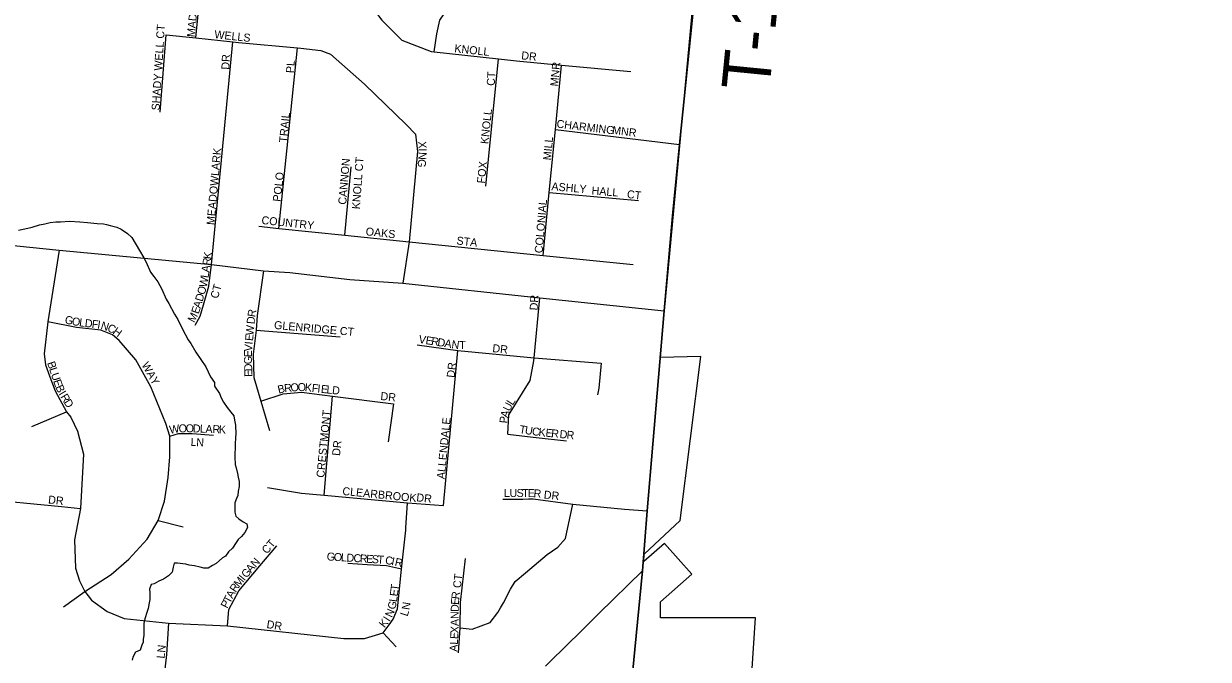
# Model space of a CAD drawing. Extents: x 1310247 to 1552180, y 377264 to 706493.
# Drawn here: x 1441493 to 1448897, y 490170 to 494144 of the extents above; entities that cross this region are included whole.
import ezdxf

# ---------------------------------------------------------------- set-up
doc = ezdxf.new("R2010")
doc.units = 0
for name, color, linetype in [('GM_X_Adjacent_County', 7, 'Continuous'), ('GM_X_Corporation', 7, 'Continuous'), ('GM_X_County', 7, 'Continuous'), ('GM_X_Minor_River', 7, 'Continuous'), ('GM_X_Township', 7, 'Continuous'), ('GM_X_Township_Road', 7, 'Continuous'), ('GM_X_Township_Road_Text', 7, 'Continuous'), ('GM_X_Township_Subdivision', 7, 'Continuous'), ('GM_X_Township_Subdivision_Text', 7, 'Continuous'), ('GM_X_US_Route', 7, 'Continuous')]:
    doc.layers.add(name, color=color, linetype=linetype)

msp = doc.modelspace()

# ---------------------------------------------------------------- linework, layer by layer
at = {"layer": 'GM_X_Adjacent_County'}
msp.add_lwpolyline([(1444758.9, 484386.7), (1444847.2, 485340), (1444871.9, 485606.9), (1444945, 486395.4), (1445051.2, 487540.6), (1445054.9, 487578.1), (1445360.5, 490723.4), (1445389.8, 491098.1), (1445497, 492347.4), (1445549.2, 492941.9), (1445592.7, 493387.5), (1445681.3, 494266.4), (1445732.6, 494862.7), (1445785.8, 495446.6), (1445993, 497703.6), (1446026.9, 498075.2), (1446211.6, 500082.3), (1446320.8, 501270), (1446353.3, 501607.9), (1446491.2, 503041.2)], dxfattribs=at)
at = {"layer": 'GM_X_Corporation'}
msp.add_lwpolyline([(1449213.9, 489565.2), (1448718.7, 488633.8), (1447946.3, 488728.6), (1447946.3, 489474.1), (1446677.2, 489572.9), (1446654.2, 489182.6), (1446017.2, 489196.3), (1446083.4, 489751.4), (1446023.8, 489764), (1446066.6, 490429.5), (1445474.1, 490429.5), (1445474.1, 490529.5), (1445668.9, 490702.2), (1445499.3, 490893.6), (1445370.2, 490780.2), (1445371.7, 490827.7), (1445596.3, 491036.6), (1445726.4, 492063.1), (1445470.2, 492057.2), (1445876.5, 496431.2)], dxfattribs=at)
at = {"layer": 'GM_X_County'}
msp.add_lwpolyline([(1446491.2, 503041.2), (1446353.3, 501607.9), (1446320.8, 501270), (1446211.6, 500082.3), (1446026.9, 498075.2), (1445993, 497703.6), (1445785.8, 495446.6), (1445732.6, 494862.7), (1445681.3, 494266.4), (1445592.7, 493387.5), (1445549.2, 492941.9), (1445497, 492347.4), (1445389.8, 491098.1), (1445360.5, 490723.4), (1445054.9, 487578.1), (1445051.2, 487540.6), (1444945, 486395.4), (1444871.9, 485606.9), (1444847.2, 485340), (1444758.9, 484386.7)], dxfattribs=at)
at = {"layer": 'GM_X_Minor_River'}
for points in [[(1441461.3, 492853.2), (1441519.9, 492865.4), (1441546.1, 492870.6), (1441592.7, 492885.3), (1441625, 492892.3), (1441659.4, 492901.3), (1441693.6, 492904.3), (1441723.8, 492905.3), (1441780.1, 492909.6), (1441844.1, 492903.7), (1441892.2, 492900.2), (1441952.2, 492894.3), (1441992.3, 492893.1), (1442010.3, 492888.6), (1442034.1, 492881.8), (1442076, 492870.5), (1442101.7, 492859.7), (1442143.1, 492832.3), (1442168.4, 492807.5), (1442218.2, 492725.7), (1442244.9, 492678.7), (1442258.2, 492652.2), (1442286.4, 492589.1), (1442307.7, 492562.4), (1442330.8, 492529.5), (1442357.6, 492484.6), (1442383.8, 492421.5), (1442401.1, 492394.9), (1442435.3, 492327.6), (1442456.4, 492294.9), (1442486.7, 492233.8), (1442520.8, 492166.5), (1442538.2, 492143.9), (1442568.8, 492090.8), (1442632.3, 491998.5), (1442660.5, 491935.4), (1442685.6, 491900.5), (1442686.9, 491876.4), (1442717.7, 491831.3), (1442726.9, 491804.9), (1442742.1, 491776.4), (1442765.3, 491743.6), (1442788.5, 491714.8), (1442805.9, 491692.1), (1442811.1, 491663.9), (1442816.2, 491633.6), (1442818.6, 491577.3), (1442818, 491559.3), (1442814.7, 491513.2), (1442812.3, 491433), (1442815, 491386.8), (1442822.4, 491366.5), (1442829.4, 491332.1), (1442834.7, 491307.9), (1442840, 491281.7), (1442841, 491249.5)], [(1442841, 491249.5), (1442834.2, 491221.6), (1442831.4, 491193.6), (1442822.8, 491175.8), (1442814, 491148), (1442812.3, 491089.8), (1442819.6, 491065.5), (1442837.1, 491046.9), (1442864.7, 491030), (1442888.4, 491017.2), (1442891.7, 490993.1), (1442874.7, 490961.5), (1442854, 490938), (1442833.3, 490918.6), (1442820.7, 490900.9), (1442797.6, 490865.5), (1442772.9, 490842.2), (1442754, 490814.6), (1442735.6, 490803.1), (1442696.4, 490768.2), (1442674, 490756.9), (1442645.4, 490739.7), (1442619.3, 490738.5), (1442595.4, 490745.2), (1442561.6, 490754.3), (1442527.5, 490757.3), (1442507.7, 490764), (1442487.7, 490766.6), (1442453.7, 490771.6), (1442433.6, 490770.2), (1442426.9, 490746.4), (1442421.9, 490714.4), (1442399.2, 490691), (1442366.4, 490669.9), (1442338, 490658.8), (1442309.4, 490641.6), (1442289.2, 490638.2), (1442280.3, 490608.3), (1442281.7, 490586.2), (1442282.5, 490544), (1442277.8, 490522.1), (1442270.8, 490488.2), (1442264.2, 490468.3), (1442250.8, 490422.6), (1442243.9, 490392.7), (1442245.2, 490370.6), (1442243.8, 490320.4), (1442241, 490294.4), (1442240.5, 490276.4), (1442231.9, 490258.6), (1442220.9, 490226.8), (1442192.5, 490213.6), (1442175.5, 490184), (1442170.9, 490164.1)]]:
    msp.add_lwpolyline(points, dxfattribs=at)
at = {"layer": 'GM_X_Township'}
msp.add_lwpolyline([(1446491.2, 503041.2), (1446353.3, 501607.9), (1446320.8, 501270), (1446211.6, 500082.3), (1446026.9, 498075.2), (1445993, 497703.6), (1445785.8, 495446.6), (1445732.6, 494862.7), (1445681.3, 494266.4), (1445592.7, 493387.5), (1445549.2, 492941.9), (1445497, 492347.4), (1445389.8, 491098.1), (1445360.5, 490723.4), (1445054.9, 487578.1), (1445051.2, 487540.6), (1444945, 486395.4), (1444871.9, 485606.9), (1444847.2, 485340), (1444758.9, 484386.7)], dxfattribs=at)
at = {"layer": 'GM_X_Township_Road'}
for points in [[(1445639.5, 493851.8), (1445681.3, 494266.4), (1445732.6, 494862.7), (1445785.8, 495446.6), (1445833.6, 495967.5)], [(1445531.1, 492735.1), (1445549.2, 492941.9), (1445592.6, 493387.5), (1445639.5, 493851.8)], [(1437774.4, 493620), (1438322.3, 493469.7), (1439008.5, 493285.9), (1439273.8, 493215.4), (1439579.9, 493129.2), (1439710.8, 493101.7), (1440082, 493005), (1440679.8, 492841.4), (1441204.7, 492780.6), (1441714.2, 492726.8), (1442667.4, 492637.5), (1442992.2, 492599.4), (1443157.4, 492587.5), (1443532.5, 492544.6), (1443863.8, 492520.3), (1444719.2, 492429.1), (1445497, 492347.4)], [(1445480, 492149.6), (1445497, 492347.4), (1445531.1, 492735.1)], [(1445354.3, 490658.8), (1445360.5, 490723.4), (1445389.8, 491098.1), (1445480, 492149.6)], [(1444837.4, 485233.9), (1444847.2, 485340), (1444871.9, 485606.9), (1444945, 486395.5), (1445051.2, 487540.6), (1445054.9, 487578.2), (1445354.3, 490658.8)]]:
    msp.add_lwpolyline(points, dxfattribs=at)
at = {"layer": 'GM_X_Township_Subdivision'}
for points in [[(1443474.7, 494549.8), (1443526.5, 494442.8), (1443613.9, 494324.9), (1443731.8, 494165.8), (1443857, 494040.6), (1444040.7, 493970.2), (1444059, 493968.2), (1444460, 493924.2), (1444572.5, 493911.8), (1444855.1, 493885.1), (1445288.1, 493844.2)], [(1442569.2, 494054.1), (1442589, 494245.3), (1442590, 494255.5)], [(1444059, 493968.2), (1444075.7, 494079.4), (1444093.9, 494165.3), (1444120.4, 494205.1)], [(1442346, 493590.6), (1442384.6, 494073.1)], [(1442384.6, 494073.1), (1442569.2, 494054.1), (1442800.1, 494030.4), (1442835.4, 494026.7), (1443204.6, 493992.4), (1443225.1, 493990.5), (1443349.7, 493975.6), (1443411.9, 493952.3), (1443623.1, 493765.7), (1443883.9, 493513.7), (1443941.9, 493453.6), (1443954.2, 493343.7), (1443902.4, 492780), (1443863.8, 492520.3)], [(1442667.4, 492637.5), (1442800.1, 494030.4)], [(1443089, 492863.7), (1443204.6, 493992.4)], [(1444381, 493128.5), (1444460, 493924.2)], [(1444739.8, 492693.8), (1444778, 493088.3), (1444816.1, 493482.3), (1444855.1, 493885.1)], [(1444816.1, 493482.3), (1445592.6, 493387.5)], [(1443499.9, 492821.4), (1443539.2, 493249.5)], [(1444778, 493088.3), (1445336.5, 493037.3)], [(1442963.6, 492876.6), (1443089, 492863.7), (1443499.9, 492821.4), (1443902.4, 492780), (1444739.8, 492693.8), (1445302.2, 492637.4)], [(1441714.2, 492726.8), (1441643.9, 492278.6), (1441621.8, 492079.3), (1441628.8, 492009.9), (1441656.5, 491936.3), (1441689.5, 491848.6), (1441760.6, 491716.7), (1441787.4, 491683.2), (1441830, 491596.9), (1441866.4, 491451.2), (1441849.1, 491112), (1441811, 490916.8), (1441817.9, 490739.8), (1441842.2, 490660), (1441876.4, 490593.2), (1441916.8, 490538.5), (1442015.7, 490469.1), (1442121.5, 490424), (1442399.1, 490395.4), (1442766.8, 490378.9), (1443493.3, 490299.9), (1443622.8, 490299.9), (1443739.4, 490334.9)], [(1442564.7, 492259), (1442595.9, 492314.4), (1442617.9, 492385.9), (1442650.6, 492502.9), (1442667.4, 492637.5)], [(1442992.2, 492599.4), (1442952.5, 492318.8), (1442945.5, 492226.8), (1442928.2, 492077.6), (1442931.6, 491931.8), (1442975, 491783.8), (1443028.8, 491600.4)], [(1444519, 491577.9), (1444526.3, 491698.8), (1444658.6, 491912), (1444682.1, 492034.7), (1444683.7, 492054.5), (1444719.2, 492429.1)], [(1441876.4, 490593.2), (1442039.9, 490699.9), (1442151, 490795.3), (1442265.5, 490920.2), (1442334.9, 491038.2), (1442373, 491158), (1442397.3, 491307.2), (1442406, 491435.6), (1442406, 491565.7), (1442381.6, 491644), (1442288.6, 491873), (1442194.1, 492041.8), (1442090.2, 492161.8), (1442048.6, 492199), (1441975.7, 492227.8), (1441823.1, 492245.1), (1441643.9, 492278.6)], [(1442945.5, 492226.8), (1443472.3, 492186.7)], [(1443953.4, 492135.7), (1444206.7, 492101), (1444683.7, 492054.5), (1445101.9, 492021.2)], [(1444117.1, 491132), (1444206.7, 492101)], [(1445101.9, 492021.2), (1445087.2, 491865.8), (1445080.6, 491823.1)], [(1442975, 491783.8), (1443115.5, 491829.5), (1443230, 491839.9), (1443424.3, 491815.6), (1443805.1, 491766.9)], [(1443371.4, 491195.1), (1443424.3, 491815.6)], [(1443805.1, 491766.9), (1443771.5, 491528.3)], [(1441543.8, 491624.7), (1441760.6, 491716.7)], [(1442406, 491565.7), (1442460.9, 491581.4), (1442546.6, 491581.1), (1442679.3, 491570.1)], [(1444519, 491577.9), (1444676.5, 491559.3)], [(1444676.5, 491559.3), (1444696, 491557.1), (1444886.8, 491536.2)], [(1443018.2, 491243.6), (1443229.2, 491207.8), (1443371.4, 491195.1), (1443892.8, 491148.7), (1444117.1, 491132)], [(1440522, 491207.4), (1440846.4, 491186.6), (1441050.1, 491190), (1441384.9, 491157.6), (1441729.4, 491124.1), (1441849.1, 491112)], [(1443882.7, 490990.9), (1443892.8, 491148.7)], [(1444487.8, 491171.1), (1444612.8, 491171.2), (1444647.7, 491172.5)], [(1444647.7, 491172.5), (1444676.9, 491173.6), (1444925, 491139.7), (1445247.6, 491108.5), (1445389.8, 491098.1)], [(1444473.7, 490492.3), (1444491.2, 490522.1), (1444536.3, 490608.9), (1444565.8, 490656.5), (1444630, 490709.5), (1444765.4, 490824.1), (1444831.3, 490871.7), (1444879.9, 490924.7), (1444925, 491139.7)], [(1442334.9, 491038.2), (1442489.8, 490998.8)], [(1443739.4, 490334.9), (1443777.8, 490384.6), (1443802.4, 490421.3), (1443830.1, 490484.3), (1443855.1, 490732.5), (1443881.8, 490977.4), (1443882.7, 490990.9)], [(1442766.8, 490378.9), (1442775.5, 490481.3), (1442838, 490597.5), (1442968.3, 490755), (1443074.5, 490878.4)], [(1444210.2, 490209.8), (1444220.6, 490366), (1444224.1, 490525.6), (1444255.3, 490799.8)], [(1443855.1, 490732.5), (1443760.6, 490755), (1443640.1, 490761), (1443518.8, 490768.4)], [(1441876.4, 490593.2), (1441875.1, 490592.3), (1441743.2, 490496.1)], [(1444220.6, 490366), (1444296.9, 490359), (1444408, 490400.7), (1444456.6, 490463.1), (1444473.7, 490492.3)], [(1442399.1, 490395.4), (1442386.9, 490199.3), (1442359.3, 489964.3)], [(1443739.4, 490334.9), (1443822.3, 490247.3)]]:
    msp.add_lwpolyline(points, dxfattribs=at)
at = {"layer": 'GM_X_US_Route'}
for points in [[(1444981.7, 490350.7), (1445088.1, 490455.4), (1445360.5, 490723.4)], [(1444754.4, 490127.2), (1444782.4, 490154.5), (1444981.7, 490350.7)]]:
    msp.add_lwpolyline(points, dxfattribs=at)

# ---------------------------------------------------------------- texts
at = {"layer": 'GM_X_Township_Road_Text'}
msp.add_text('T-11', height=300, rotation=84.36034, dxfattribs=at).set_placement((1446152.6, 493716.3))
at = {"layer": 'GM_X_Township_Subdivision_Text'}
for s, rotation, p in [('MADDOX', 84.642, (1442562.5, 494057.7)), ('SHADY WELL CT', 86.39154, (1442342.5, 493599.9)), ('WELLS', 353.92445, (1442683.1, 494053.1)), ('KNOLL', 353.92842, (1444183.3, 493965.1)), ('DR', 353.99459, (1444601.3, 493921.1)), ('DR', 86.98328, (1442778.1, 493855)), ('PL', 86.42578, (1443182.9, 493833.1)), ('MNR', 84.47166, (1444832.9, 493749.8)), ('CT', 86.82184, (1444436.9, 493753.8)), ('KNOLL', 83.99039, (1444397.3, 493389.1)), ('TRAIL', 84.40165, (1443138.9, 493397.8)), ('CHARMING', 353.15815, (1444821.4, 493494.3)), ('MNR', 352.87204, (1445169, 493454.6)), ('X', 273.86061, (1443958.5, 493406.4)), ('MILL', 84.80601, (1444788.9, 493287.8)), ('MEADOWLARK', 84.90743, (1442685.7, 492883)), ('CANNON', 85.15496, (1443508.5, 493010.5)), ('KNOLL CT', 85.79367, (1443594.3, 492982.1)), ('G', 265.60213, (1443959.4, 493298.5)), ('N', 266.86199, (1443961.8, 493342.2)), ('I', 271.00548, (1443961.4, 493363.2)), ('FOX', 83.88393, (1444375.3, 493142.7)), ('POLO', 83.47755, (1443099.3, 493028.4)), ('ASHLY', 355.02841, (1444790.3, 493102.7)), ('HALL', 355.36422, (1445041.1, 493076.3)), ('CT', 353.29389, (1445261.4, 493054.3)), ('COLONIAL', 85.17075, (1444736.1, 492706.9)), ('COUNTRY', 353.94583, (1442977.7, 492891.5)), ('OAKS', 354.05417, (1443628.9, 492821.1)), ('STA', 353.42141, (1444196.6, 492763.9)), ('K', 82.02908, (1442664.7, 492668.9)), ('A', 82.02908, (1442653.1, 492586.2)), ('R', 82.03303, (1442659.2, 492629.7)), ('W', 79.40459, (1442637.4, 492492.6)), ('L', 82.07181, (1442648.3, 492551.3)), ('O', 73.27484, (1442623.3, 492444.8)), ('CT', 74.48321, (1442707.2, 492421.2)), ('D', 73.27484, (1442610.7, 492402.6)), ('DR', 86.82184, (1444705.3, 492350.2)), ('M', 63.06432, (1442559.4, 492271)), ('E', 71.75069, (1442586.5, 492325.7)), ('A', 73.23931, (1442598, 492360.5)), ('R', 79.96669, (1442940, 492306.2)), ('G', 347.59685, (1441746.8, 492270.9)), ('O', 349.16377, (1441791.2, 492261.1)), ('L', 352.93592, (1441838, 492252.3)), ('D', 353.31614, (1441873.2, 492247.9)), ('F', 353.30533, (1441916.9, 492242.8)), ('I', 351.28874, (1441951.4, 492238.8)), ('N', 343.05476, (1441971.3, 492235.9)), ('C', 336.41235, (1442012, 492223.6)), ('W', 84.75533, (1442929.5, 492193.3)), ('D', 84.5493, (1442935.9, 492263.4)), ('GLENRIDGE CT', 354.90744, (1443056.7, 492235.9)), ('H', 323.95415, (1442045.8, 492209.2)), ('E', 84.75742, (1442926.3, 492158.3)), ('V', 351.07851, (1443959.4, 492147.8)), ('E', 351.06999, (1444002.8, 492141)), ('R', 351.07216, (1444037.6, 492135.5)), ('V', 85.06481, (1442920.5, 492092.6)), ('I', 84.74618, (1442924.3, 492136.4)), ('D', 351.07441, (1444076.7, 492129.4)), ('A', 351.07441, (1444120.2, 492122.6)), ('N', 352.2928, (1444164.8, 492115.6)), ('T', 358.67546, (1444214.5, 492109.2)), ('DR', 353.99459, (1444420.9, 492090.7)), ('WAY', 299.54008, (1442228.1, 492011.2)), ('G', 91.72844, (1442920.9, 492015)), ('E', 88.46992, (1442919.6, 492058.2)), ('B', 288.53479, (1441639.2, 492022.7)), ('L', 288.52999, (1441651.8, 491985.1)), ('U', 288.54127, (1441663, 491951.7)), ('D', 91.71586, (1442922.2, 491971)), ('E', 91.72164, (1442923.3, 491935.8)), ('DR', 83.99458, (1444186.3, 491928.3)), ('E', 288.52999, (1441677, 491910)), ('B', 294.46878, (1441690.2, 491871.5)), ('B', 13.67991, (1443087.1, 491830.3)), ('R', 5.87491, (1443123.8, 491839.4)), ('O', 4.17827, (1443162.8, 491843.4)), ('O', 0.17485, (1443205.7, 491846.6)), ('K', 354.19806, (1443248.4, 491846.8)), ('F', 353.868, (1443292.1, 491842.4)), ('I', 353.89571, (1443327.1, 491838.6)), ('I', 301.34611, (1441709.6, 491829.7)), ('R', 301.26782, (1441721.1, 491811)), ('E', 353.88159, (1443348.9, 491836.3)), ('L', 353.868, (1443383.9, 491832.5)), ('D', 353.88688, (1443419, 491828.7)), ('DR', 353.9889, (1443721.3, 491791.5)), ('D', 301.26174, (1441741.6, 491777.1)), ('U', 63.10291, (1444530.2, 491716)), ('L', 57.72348, (1444549.5, 491754.1)), ('CRESTMONT', 84.55886, (1443372.1, 491303.4)), ('ALLENDALE', 84.49492, (1444124.7, 491294.6)), ('P', 84.62058, (1444516, 491643.4)), ('A', 73.86174, (1444518.8, 491676)), ('W', 7.97793, (1442407.2, 491580.1)), ('O', 1.5083, (1442462.4, 491588)), ('O', 359.50825, (1442505.9, 491589.1)), ('D', 358.01076, (1442549.6, 491588.7)), ('L', 357.70448, (1442593.5, 491587.2)), ('A', 357.7072, (1442628.6, 491585.8)), ('R', 357.70454, (1442672.6, 491584.1)), ('K', 357.70459, (1442712.2, 491582.5)), ('T', 350.9599, (1444588.6, 491584.6)), ('U', 350.97248, (1444623.4, 491579.1)), ('C', 352.02461, (1444667.8, 491572)), ('K', 354.29873, (1444709.2, 491566.3)), ('E', 354.6175, (1444753.3, 491561.9)), ('R', 354.6132, (1444788.3, 491558.6)), ('D', 354.6035, (1444840.9, 491553.6)), ('R', 354.61356, (1444884.7, 491549.5)), ('L', 357.69083, (1442536.2, 491504.1)), ('N', 357.16816, (1442571.2, 491502.6)), ('DR', 83.98829, (1443470, 491439.8)), ('CLEARBROOK', 354.47201, (1443483.6, 491197.5)), ('L', 359.95902, (1444494.7, 491184.3)), ('U', 359.95629, (1444529.9, 491184.3)), ('S', 359.95902, (1444573.9, 491184.3)), ('T', 359.95902, (1444609.1, 491184.3)), ('E', 358.74306, (1444644, 491184.2)), ('R', 355.62458, (1444678.5, 491183.5)), ('DR', 353.99459, (1444742.1, 491175.5)), ('DR', 353.99399, (1441644.5, 491144.5)), ('DR', 353.99459, (1443945.7, 491157.9)), ('CT', 49.40063, (1443013.6, 490824.7)), ('N', 47.99166, (1442942.6, 490741.1)), ('G', 356.59953, (1443386.4, 490788.3)), ('O', 356.60941, (1443430.4, 490785.7)), ('L', 356.59664, (1443474.3, 490783.1)), ('D', 356.60941, (1443509.4, 490781)), ('C', 356.59789, (1443553.4, 490778.4)), ('R', 356.60532, (1443592.9, 490776.1)), ('E', 356.59664, (1443632.4, 490773.7)), ('S', 356.60744, (1443667.6, 490771.6)), ('T', 356.59664, (1443702.7, 490769.5)), ('C', 350.84307, (1443749.7, 490766.5)), ('I', 348.04719, (1443788.2, 490760.3)), ('R', 347.73987, (1443809.6, 490755.7)), ('G', 50.15738, (1442886.5, 490673.9)), ('A', 50.16084, (1442914.7, 490707.7)), ('CT', 83.65713, (1444225.7, 490612.8)), ('R', 57.01379, (1442818.2, 490584.4)), ('M', 50.46261, (1442838.9, 490616.4)), ('I', 50.15245, (1442872.4, 490657.1)), ('T', 82.86481, (1443834.8, 490595.9)), ('T', 62.45139, (1442782.2, 490515.2)), ('A', 62.46288, (1442798.5, 490546.5)), ('L', 82.55303, (1443825.8, 490525.8)), ('E', 82.88435, (1443830.4, 490561)), ('R', 82.62198, (1444215.1, 490543)), ('P', 62.4635, (1442765.9, 490484)), ('N', 65.97584, (1443794.2, 490427.4)), ('G', 77.69052, (1443815.6, 490478.2)), ('N', 80.61079, (1443904.5, 490475.9)), ('D', 89.78143, (1444212.6, 490465.5)), ('E', 85.93967, (1444212.7, 490508.6)), ('DR', 351.0318, (1443009, 490365.8)), ('K', 52.08092, (1443748.5, 490362.9)), ('I', 57.35461, (1443778.5, 490401.7)), ('L', 72.40312, (1443892.1, 490434.9)), ('A', 89.72245, (1444212.3, 490377.4)), ('N', 89.89703, (1444212.5, 490421.5)), ('E', 86.66482, (1444208.3, 490295.3)), ('X', 87.62282, (1444210.4, 490331.4)), ('A', 86.66498, (1444203.7, 490216.3)), ('L', 86.66482, (1444206.3, 490260.2)), ('LN', 83.98889, (1442373.3, 490172.7))]:
    msp.add_text(s, height=50, rotation=rotation, dxfattribs=at).set_placement(p)

doc.saveas('drawing.dxf')
